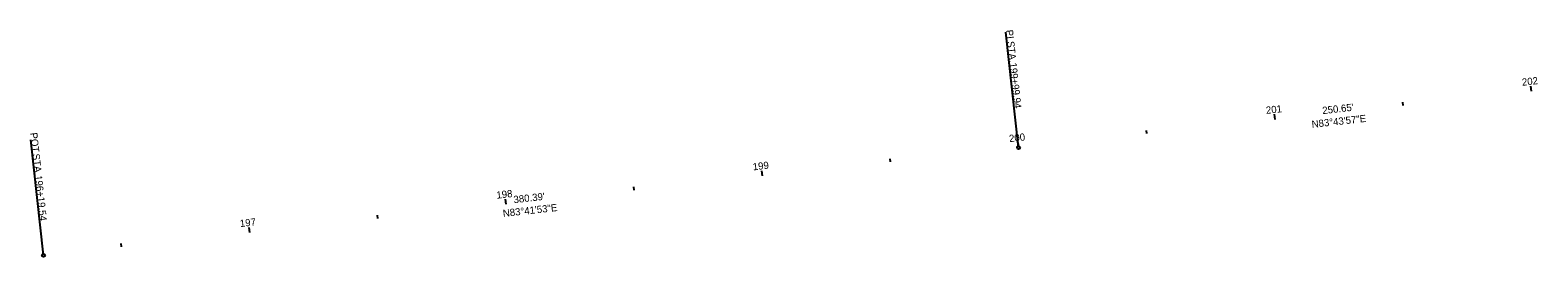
# Model space of a CAD drawing. Extents: x 1600023 to 1602131, y 285824 to 287284.
# Drawn here: x 1600023 to 1600607, y 286534 to 286622 of the extents above; entities that cross this region are included whole.
import ezdxf

# ---------------------------------------------------------------- set-up
doc = ezdxf.new("R2010")
doc.units = 0
for name, color, linetype in [('_CIVIL_CONSTRUCTION', 7, 'Continuous'), ('GE_P_Alignment', 7, 'Continuous'), ('PF_P_Grade_Line', 7, 'Continuous'), ('SC_Scratch6', 7, 'Continuous')]:
    doc.layers.add(name, color=color, linetype=linetype)

msp = doc.modelspace()

# ---------------------------------------------------------------- linework, layer by layer
at = {"layer": '_CIVIL_CONSTRUCTION'}
for p, q in [((1600406.13, 286576.06), (1600401.22, 286620.8)), ((1600028.03, 286534.31), (1600023.1, 286579.04))]:
    msp.add_line(p, q, dxfattribs=at)
for centre in [(1600406.13, 286576.06), (1600028.03, 286534.31)]:
    msp.add_circle(centre, 0.6, dxfattribs=at)
at = {"layer": 'SC_Scratch6'}
for p, q in [((1600605, 286597.91), (1600604.78, 286599.89)), ((1600555.3, 286592.45), (1600555.17, 286593.64)), ((1600505.59, 286586.99), (1600505.38, 286588.98)), ((1600455.89, 286581.53), (1600455.76, 286582.72)), ((1600406.19, 286576.07), (1600405.97, 286578.06)), ((1600306.8, 286565.1), (1600306.58, 286567.08)), ((1600356.49, 286570.58), (1600356.36, 286571.78)), ((1600257.1, 286559.61), (1600256.97, 286560.8)), ((1600207.4, 286554.12), (1600207.18, 286556.11)), ((1600157.7, 286548.63), (1600157.57, 286549.82)), ((1600108.01, 286543.14), (1600107.79, 286545.13)), ((1600058.31, 286537.65), (1600058.18, 286538.85))]:
    msp.add_line(p, q, dxfattribs=at)

# ---------------------------------------------------------------- texts
at = {"layer": '_CIVIL_CONSTRUCTION'}
for s, rotation, p in [('PI', 276.26752, (1600401.17, 286621.61)), (' STA. ', 276.26752, (1600401.54, 286618.24)), ('199+99.94', 276.26752, (1600402.57, 286608.85)), ('POT', 276.30182, (1600022.84, 286581.75)), (' STA. ', 276.30182, (1600023.63, 286574.59)), ('196+19.54', 276.30182, (1600024.67, 286565.2))]:
    msp.add_text(s, height=2.8, rotation=rotation, dxfattribs=at).set_placement(p)
at = {"layer": 'GE_P_Alignment'}
for s, rotation, p in [('N83°43\'57"E', 6.26752, (1600519.93, 286583.73)), ('N83°41\'53"E', 6.30182, (1600206.31, 286549.17))]:
    msp.add_text(s, height=2.8, rotation=rotation, dxfattribs=at).set_placement(p)
at = {"layer": 'PF_P_Grade_Line'}
for s, rotation, p in [("250.65'", 6.26752, (1600524.06, 286589.06)), ("380.39'", 6.30182, (1600210.44, 286554.5))]:
    msp.add_text(s, height=2.8, rotation=rotation, dxfattribs=at).set_placement(p)
at = {"layer": 'SC_Scratch6'}
for s, rotation, p in [('202', 6.26752, (1600601.46, 286600.03)), ('201', 6.26752, (1600502.19, 286589.13)), ('200', 6.26752, (1600402.59, 286578.19)), ('199', 6.30182, (1600303.22, 286567.22)), ('198', 6.30182, (1600203.81, 286556.24)), ('197', 6.30182, (1600104.34, 286545.25))]:
    msp.add_text(s, height=2.8, rotation=rotation, dxfattribs=at).set_placement(p)

doc.saveas('drawing.dxf')
